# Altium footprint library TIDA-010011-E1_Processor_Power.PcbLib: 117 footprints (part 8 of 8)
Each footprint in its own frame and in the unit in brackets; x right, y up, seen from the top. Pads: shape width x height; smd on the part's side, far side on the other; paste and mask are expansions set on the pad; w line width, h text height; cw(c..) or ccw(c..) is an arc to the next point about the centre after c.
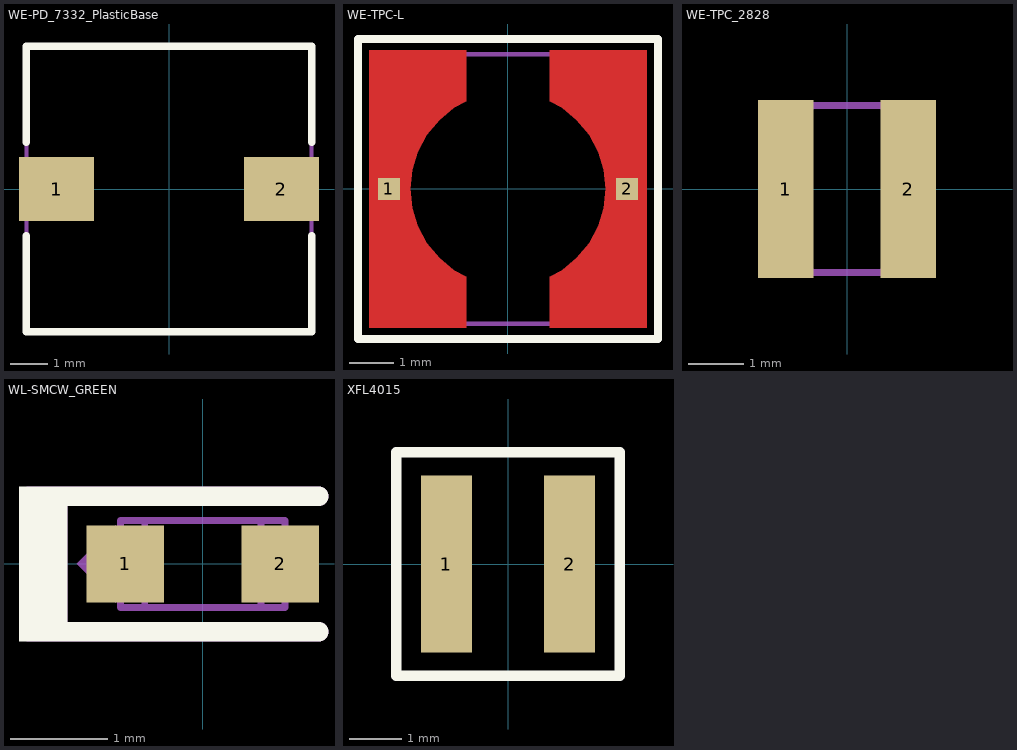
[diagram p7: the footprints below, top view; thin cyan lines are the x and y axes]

## WE-PD_7332_PlasticBase [mm] "SMD Inductor, 2-Leads, Body 7,3x7,3mm"
height 3.2
pads (2):
  rect 2x1.7 smd: 1(-3,0) 2(3,0)
Top Overlay:
  lines w0.2: -3.8,-1.25 -3.8,-3.8 3.8,-3.8 3.8,-1.25 ; -3.8,1.25 -3.8,3.8 3.8,3.8 3.8,1.25
Mechanical 5:
  lines w0.1: -3.8,-3.8 3.8,-3.8 3.8,3.8 -3.8,3.8 -3.8,-3.8
  text ".Designator" at -0.584,-0.305 h0.51
3D body "744778910.stp": height 3.19, standoff -0.01, extent -3.65,-3.65 3.65,3.65

## WE-TPC-L [mm] "Wurth Elektronik recommended land pattern, 2009-01-15"
height 2
pads (2):
  rect 0.5x0.5 smd: 1(-2.7,0) 2(2.7,0)
Top Layer:
  region: 0.95,3.15 0.95,1.987 1.228,1.838 1.563,1.563 1.838,1.228 2.042,0.846 2.168,0.431 2.211,0 2.168,-0.431 2.042,-0.846 1.838,-1.228 1.563,-1.563 1.228,-1.838 0.95,-1.987 0.95,-3.15 3.15,-3.15 3.15,3.15
  region: -0.95,3.15 -0.95,1.987 -1.228,1.838 -1.563,1.563 -1.838,1.228 -2.042,0.846 -2.168,0.431 -2.211,0 -2.168,-0.431 -2.042,-0.846 -1.838,-1.228 -1.563,-1.563 -1.228,-1.838 -0.95,-1.987 -0.95,-3.15 -3.15,-3.15 -3.15,3.15
Top Overlay:
  lines w0.178: -3.4,-3.4 0,-3.4 3.4,-3.4 3.4,0 3.4,3.4 0,3.4 -3.4,3.4 -3.4,0 -3.4,-3.4
Top Paste:
  region: -0.95,3.15 -0.95,1.987 -1.228,1.838 -1.563,1.563 -1.838,1.228 -2.042,0.846 -2.168,0.431 -2.211,0 -2.168,-0.431 -2.042,-0.846 -1.838,-1.228 -1.563,-1.563 -1.228,-1.838 -0.95,-1.987 -0.95,-3.15 -3.15,-3.15 -3.15,3.15
  region: 0.95,3.15 0.95,1.987 1.228,1.838 1.563,1.563 1.838,1.228 2.042,0.846 2.168,0.431 2.211,0 2.168,-0.431 2.042,-0.846 1.838,-1.228 1.563,-1.563 1.228,-1.838 0.95,-1.987 0.95,-3.15 3.15,-3.15 3.15,3.15
Top Solder:
  region: -0.95,3.15 -0.95,1.987 -1.228,1.838 -1.563,1.563 -1.838,1.228 -2.042,0.846 -2.168,0.431 -2.211,0 -2.168,-0.431 -2.042,-0.846 -1.838,-1.228 -1.563,-1.563 -1.228,-1.838 -0.95,-1.987 -0.95,-3.15 -3.15,-3.15 -3.15,3.15
  region: 0.95,3.15 0.95,1.987 1.228,1.838 1.563,1.563 1.838,1.228 2.042,0.846 2.168,0.431 2.211,0 2.168,-0.431 2.042,-0.846 1.838,-1.228 1.563,-1.563 1.228,-1.838 0.95,-1.987 0.95,-3.15 3.15,-3.15 3.15,3.15
Mechanical 5:
  lines w0.102: -3.05,-1.78 ccw(c-1.78,-1.78) -1.78,-3.05 1.78,-3.05 ccw(c1.78,-1.78) 3.05,-1.78 3.05,1.78 ccw(c1.78,1.78) 1.78,3.05 -1.78,3.05 ccw(c-1.78,1.78) -3.05,1.78 -3.05,-1.78
  text ".Designator" at -0.025,0.457 h0.51
3D body: height 2, standoff 0, extent -3.049,-3.049 3.049,3.049

## WE-TPC_2828 [mm] "WURTH"
height 3
pads (2):
  rect 1x3.2 smd: 1(-1.1,0) 2(1.1,0)
Mechanical 5:
  lines w0.127: -1.5,-0.621 -1.5,0.621 -0.621,1.5 0.621,1.5 1.5,0.621 1.5,-0.621 0.621,-1.5 -0.621,-1.5 -1.5,-0.621
  text ".Designator" at 0.358,-0.374 h0.51
3D body "WE-TPC_2828.stp": height 3, standoff 0, extent -1.5,-1.5 1.5,1.5

## WL-SMCW_GREEN [mm] "WURTH"
height 0.8
pads (2):
  rect 0.8x0.8 smd: 1(-0.8,0) 2(0.8,0)
Top Overlay:
  rectangle: -1.899,-0.8 -1.399,0.8
  lines w0.2: -1.6,-0.7 1.2,-0.7 ; -1.6,0.7 1.2,0.7
Mechanical 5:
  region: -0.9,-0.4 -0.9,0.4 -1.3,0
  lines w0.2: -1.65,-0.7 -1.65,0.55 ; 1.2,-0.7 -1.5,-0.7 ; 1.2,0.7 -1.5,0.7 ; -1.5,-0.7 -1.8,-0.7 -1.8,0.7 -1.5,0.7 ; -1.5,-0.7 -1.5,0.7
  text ".Designator" at -0.356,-0.229 h0.51
Mechanical 13:
  lines w0.07: -0.6,-0.45 -0.6,0.45 ; 0.6,-0.45 0.6,0.45 ; -0.85,-0.45 0.85,-0.45 0.85,0.45 -0.85,0.45 -0.85,-0.45
3D body: height 0.8, standoff 0.35, extent -0.599,-0.449 0.599,0.449
3D body: height 0.35, standoff 0, extent 0.601,-0.449 0.849,0.449
3D body: height 0.35, standoff 0, extent -0.599,-0.449 0.599,0.449
3D body: height 0.35, standoff 0, extent -0.849,-0.449 -0.601,0.449

## XFL4015 [mm] "SMD, 2-Leads, Body 4x4mm"
height 1.6
pads (2):
  rect 0.98x3.4 smd: 1(-1.185,0) 2(1.185,0)
Top Overlay:
  lines w0.2: -2.15,-2.15 2.15,-2.15 2.15,2.15 -2.15,2.15 -2.15,-2.15
Mechanical 5:
  lines w0.1: -2.15,-2.15 2.15,-2.15 2.15,2.15 -2.15,2.15 -2.15,-2.15
  text ".Designator" at 0.051,-0.635 h0.51
3D body: height 1.6, standoff 0, extent -2.15,-2.15 2.15,2.15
